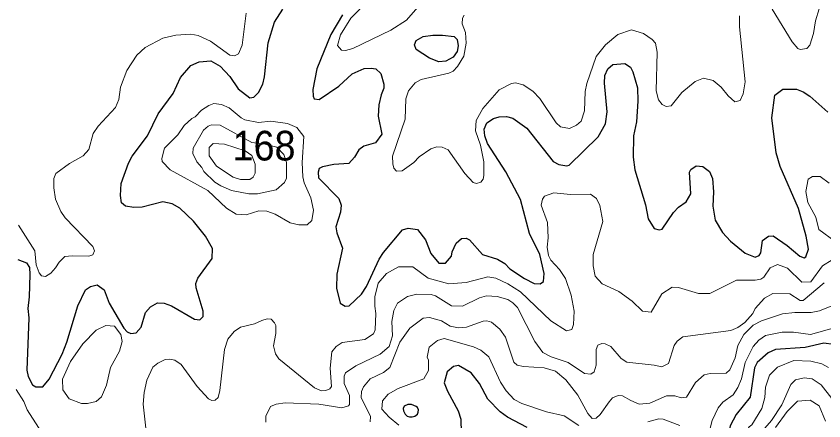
# Model space of a CAD drawing. Extents: x 673.6 to 698.9, y 7012 to 7040.1.
# Drawn here: x 673.738 to 675.914, y 7019.139 to 7020.23 of the extents above; entities that cross this region are included whole.
import ezdxf

# ---------------------------------------------------------------- set-up
doc = ezdxf.new("R2010")
doc.units = 0
doc.header["$LTSCALE"] = 0.032
doc.layers.add('1', color=7, linetype='Continuous', lineweight=25)
doc.layers.add('2', color=7, linetype='Continuous', lineweight=13)
doc.layers.add('21', color=7, linetype='Continuous')

msp = doc.modelspace()

# ---------------------------------------------------------------- linework, layer by layer
at = {"layer": '1'}
for points in [[(673.7433, 7019.5738), (673.7662, 7019.5649), (673.7745, 7019.5519), (673.7754, 7019.5338), (673.7737, 7019.473), (673.7697, 7019.4419), (673.7722, 7019.417), (673.7673, 7019.2755), (673.7709, 7019.2586), (673.7827, 7019.2356), (673.7915, 7019.2307), (673.8099, 7019.2308), (673.827, 7019.2516), (673.8619, 7019.3187), (673.8745, 7019.3507), (673.9043, 7019.4486), (673.9254, 7019.4924), (673.9389, 7019.5012), (673.9568, 7019.5058), (673.975, 7019.4919), (673.9892, 7019.4563), (674.0281, 7019.3886), (674.0377, 7019.3786), (674.0476, 7019.3742), (674.0617, 7019.3763), (674.0747, 7019.391), (674.0871, 7019.4306), (674.0998, 7019.4463), (674.119, 7019.4572), (674.1367, 7019.4565), (674.1567, 7019.4491), (674.2189, 7019.4126), (674.2328, 7019.4113), (674.242, 7019.4201), (674.2421, 7019.4343), (674.2228, 7019.4978), (674.2225, 7019.5095), (674.2279, 7019.5238), (674.2661, 7019.5766), (674.2668, 7019.6033), (674.2484, 7019.6365), (674.2162, 7019.6773), (674.1792, 7019.7119), (674.1583, 7019.7236), (674.1337, 7019.7292), (674.0778, 7019.7147), (674.0552, 7019.7138), (674.0329, 7019.7172), (674.0225, 7019.7267), (674.0194, 7019.7465), (674.0213, 7019.7791), (674.0413, 7019.8338), (674.0511, 7019.8519), (674.0924, 7019.9074), (674.1207, 7019.9663), (674.1616, 7020.0211), (674.1812, 7020.0644), (674.2085, 7020.0967), (674.2311, 7020.1066), (674.2631, 7020.1093), (674.2882, 7020.0949), (674.3142, 7020.0674), (674.3366, 7020.0334), (674.368, 7020.0098), (674.3786, 7020.0114), (674.3911, 7020.0238), (674.4024, 7020.0466), (674.4073, 7020.0663), (674.4172, 7020.158), (674.4341, 7020.2134), (674.4565, 7020.2484)], [(674.617, 7020.2335), (674.5862, 7020.1805), (674.548, 7020.0881), (674.5372, 7020.0318), (674.5381, 7020.0138), (674.5413, 7020.0067), (674.5548, 7020.0055), (674.6075, 7020.0406), (674.6433, 7020.0745), (674.6761, 7020.0884), (674.6941, 7020.09), (674.7075, 7020.088), (674.7209, 7020.0754), (674.7286, 7020.0463), (674.7286, 7020.0356), (674.7217, 7020.018)], [(674.6745, 7019.8789), (674.6609, 7019.869), (674.65, 7019.8497), (674.6348, 7019.8322), (674.5936, 7019.8296), (674.5631, 7019.824), (674.5541, 7019.8192), (674.5519, 7019.8095), (674.5531, 7019.7941), (674.6073, 7019.7381), (674.6135, 7019.7199), (674.6119, 7019.7014), (674.5996, 7019.6619), (674.6022, 7019.6456), (674.617, 7019.6042), (674.6022, 7019.5342), (674.6013, 7019.4964), (674.6112, 7019.4557), (674.6247, 7019.4484), (674.6355, 7019.4493), (674.6689, 7019.4806), (674.6818, 7019.5008), (674.7162, 7019.5746), (674.7276, 7019.5927), (674.7787, 7019.6535), (674.7944, 7019.6586), (674.819, 7019.6545), (674.8406, 7019.6272), (674.8551, 7019.5901), (674.8767, 7019.5643), (674.8949, 7019.5638), (674.911, 7019.5825), (674.9128, 7019.5946), (674.9237, 7019.6178), (674.9374, 7019.6306), (674.9505, 7019.6314), (674.959, 7019.6271), (674.9944, 7019.5873), (675.0343, 7019.5749), (675.0541, 7019.5634), (675.0684, 7019.5484), (675.1074, 7019.5223), (675.1333, 7019.5092), (675.1499, 7019.5085), (675.1582, 7019.5149), (675.1606, 7019.5363), (675.1487, 7019.5877), (675.1205, 7019.6443), (675.0968, 7019.7359), (675.0571, 7019.8103), (675.0082, 7019.8869), (675.0007, 7019.9069), (674.9984, 7019.9253), (675.0062, 7019.9418), (675.0244, 7019.954), (675.0393, 7019.9586), (675.059, 7019.9595), (675.0764, 7019.9548), (675.1137, 7019.9277), (675.1851, 7019.8377), (675.1999, 7019.8296), (675.2213, 7019.8264), (675.2277, 7019.8283), (675.3061, 7019.9041), (675.3253, 7019.9398), (675.3302, 7019.9718), (675.3229, 7020.049), (675.3237, 7020.0696), (675.3317, 7020.0875), (675.3458, 7020.0998), (675.3774, 7020.1024), (675.3931, 7020.092), (675.3995, 7020.0793), (675.4115, 7020.0367), (675.4131, 7020.0006), (675.409, 7019.9447), (675.4009, 7019.9073), (675.4002, 7019.8495), (675.4049, 7019.8152), (675.4336, 7019.7216), (675.4403, 7019.6838), (675.4563, 7019.6576), (675.4701, 7019.6542), (675.4785, 7019.6559), (675.5086, 7019.7006), (675.5224, 7019.7152), (675.5432, 7019.7289), (675.5552, 7019.7512), (675.5521, 7019.8095), (675.5557, 7019.816), (675.5699, 7019.826), (675.5874, 7019.8248), (675.6053, 7019.8109), (675.6136, 7019.7918), (675.6161, 7019.7561)], [(675.7021, 7019.5908), (675.7291, 7019.5799), (675.7391, 7019.5847), (675.7441, 7019.5919), (675.7488, 7019.6254), (675.7642, 7019.6371), (675.7776, 7019.6373), (675.8153, 7019.6112), (675.8492, 7019.5826), (675.8608, 7019.5785), (675.8653, 7019.5812), (675.8725, 7019.6015), (675.866, 7019.637), (675.8456, 7019.711), (675.7956, 7019.8247), (675.7854, 7019.8613), (675.774, 7019.9556), (675.7816, 7020.0171), (675.8033, 7020.0332), (675.8397, 7020.0326), (675.8577, 7020.026), (675.8758, 7020.0145), (675.9248, 7019.9712)], [(674.7217, 7020.018), (674.7155, 7019.9904), (674.7132, 7019.9603), (674.7235, 7019.9119), (674.7058, 7019.8886), (674.6745, 7019.8789)], [(675.6161, 7019.7561), (675.6146, 7019.7176), (675.6211, 7019.6802), (675.6411, 7019.6462), (675.6626, 7019.6236), (675.7021, 7019.5908)], [(675.9399, 7019.345), (675.9136, 7019.3481), (675.8631, 7019.3367), (675.7835, 7019.3308), (675.7641, 7019.3226), (675.7339, 7019.2958), (675.7272, 7019.2816), (675.7155, 7019.2027), (675.6772, 7019.1561), (675.6618, 7019.1256), (675.6419, 7019.0413), (675.6265, 7019.0236), (675.6142, 7019.0217), (675.6028, 7019.0241), (675.5668, 7019.0621), (675.5417, 7019.0746), (675.5031, 7019.0785), (675.4452, 7019.0681), (675.4056, 7019.046), (675.3679, 7019.0077)], [(675.1146, 7019.1206), (675.0616, 7019.1487), (675.042, 7019.1629), (675.0089, 7019.1974), (674.9861, 7019.2393), (674.9638, 7019.2682), (674.93, 7019.288), (674.9161, 7019.2855), (674.8994, 7019.2707), (674.8915, 7019.2414), (674.9005, 7019.2187), (674.9291, 7019.1657), (674.9364, 7019.143), (674.9379, 7019.069)]]:
    msp.add_lwpolyline(points, dxfattribs=at)
for points in [[(674.8862, 7020.1781), (674.9178, 7020.1747), (674.9261, 7020.1671), (674.929, 7020.1494), (674.9257, 7020.1349), (674.9156, 7020.1196), (674.8958, 7020.1085), (674.877, 7020.1067), (674.852, 7020.1168), (674.8159, 7020.1403), (674.811, 7020.1525), (674.8156, 7020.1638), (674.8348, 7020.1751), (674.8602, 7020.1789)], [(674.816, 7019.1777), (674.8034, 7019.1827), (674.793, 7019.1825), (674.7834, 7019.1784), (674.7808, 7019.1718), (674.7812, 7019.1657), (674.786, 7019.1573), (674.7915, 7019.1518), (674.7976, 7019.1501), (674.8047, 7019.1499), (674.8119, 7019.1518), (674.8191, 7019.1566), (674.8215, 7019.1625), (674.8217, 7019.1688), (674.8191, 7019.1751)]]:
    msp.add_lwpolyline(points, close=True, dxfattribs=at)
at = {"layer": '2'}
for points in [[(674.8204, 7020.2544), (674.7894, 7020.2191), (674.7478, 7020.1918), (674.6452, 7020.1429), (674.6255, 7020.1371), (674.6145, 7020.1377), (674.604, 7020.1507), (674.612, 7020.1797), (674.6394, 7020.2242), (674.6894, 7020.2754)], [(674.358, 7020.2378), (674.3472, 7020.1515), (674.3371, 7020.1285), (674.3265, 7020.1231), (674.314, 7020.1243), (674.2616, 7020.1626), (674.2282, 7020.1778), (674.2084, 7020.1813), (674.1684, 7020.1788)], [(674.855, 7019.8722), (674.8237, 7019.8507), (674.8097, 7019.835), (674.7777, 7019.8132), (674.7627, 7019.8123), (674.7552, 7019.8199), (674.7531, 7019.832), (674.7516, 7019.8523), (674.7859, 7019.9517), (674.7879, 7020.0071), (674.7952, 7020.0283), (674.813, 7020.0496), (674.8289, 7020.0589), (674.9034, 7020.0757), (674.9155, 7020.0814), (674.9272, 7020.0941), (674.9438, 7020.1219), (674.9506, 7020.1571), (674.9482, 7020.1853), (674.9399, 7020.2088), (674.9407, 7020.2246), (674.9452, 7020.2325)], [(675.6869, 7020.231), (675.6868, 7020.2006), (675.7016, 7020.0524), (675.6964, 7020.0207), (675.6882, 7020.0024), (675.6735, 7019.9991), (675.6557, 7020.0154), (675.6375, 7020.0384), (675.616, 7020.0567), (675.5896, 7020.0623), (675.5673, 7020.0533), (675.5308, 7020.0244), (675.5026, 7019.9883), (675.4891, 7019.9858), (675.4783, 7019.9914), (675.4683, 7020.0042), (675.4617, 7020.0286), (675.465, 7020.1328), (675.4599, 7020.1566), (675.4512, 7020.1672), (675.4279, 7020.183), (675.3957, 7020.1927), (675.3588, 7020.18), (675.3255, 7020.1527), (675.3005, 7020.1209), (675.2751, 7020.0479), (675.2711, 7020.0269), (675.2693, 7019.9743), (675.2602, 7019.9468), (675.2473, 7019.9361), (675.2288, 7019.9267), (675.2045, 7019.9317), (675.193, 7019.9422), (675.1492, 7020.0074), (675.1299, 7020.0274), (675.1043, 7020.0444), (675.0828, 7020.0497), (675.0728, 7020.0481), (675.0396, 7020.0312), (674.9953, 7019.981), (674.9771, 7019.9487), (674.9753, 7019.9204), (674.9888, 7019.8818), (674.9982, 7019.837), (674.9982, 7019.7998), (674.9957, 7019.7902), (674.9897, 7019.7827), (674.9786, 7019.7788), (674.9695, 7019.7818)], [(675.9008, 7020.2494), (675.891, 7020.217), (675.8857, 7020.1831), (675.8762, 7020.1512), (675.8679, 7020.1423), (675.8502, 7020.1396), (675.8433, 7020.1428), (675.8279, 7020.1603), (675.7749, 7020.2484)], [(674.1684, 7020.1788), (674.1333, 7020.1702), (674.0862, 7020.145), (674.063, 7020.1244), (674.0369, 7020.083), (674.019, 7020.0379)], [(674.019, 7020.0379), (674.0153, 7020.0052), (674.0058, 7019.9832), (673.9593, 7019.9336), (673.9456, 7019.9138), (673.9343, 7019.8701), (673.9192, 7019.8528), (673.8822, 7019.8329), (673.8452, 7019.8055), (673.84, 7019.792), (673.8396, 7019.7669), (673.8444, 7019.7363), (673.8584, 7019.7032), (673.8702, 7019.6864), (673.9447, 7019.6086), (673.9494, 7019.5969), (673.945, 7019.5861), (673.9344, 7019.5824), (673.8892, 7019.5839), (673.8698, 7019.5817), (673.8546, 7019.567), (673.8445, 7019.5509), (673.8318, 7019.537), (673.8177, 7019.528), (673.807, 7019.5296), (673.8004, 7019.5381), (673.7923, 7019.5598), (673.7883, 7019.597), (673.7446, 7019.6664)], [(674.9695, 7019.7818), (674.947, 7019.8052), (674.9023, 7019.8696), (674.8861, 7019.8765), (674.8716, 7019.8773), (674.855, 7019.8722)], [(675.9279, 7019.78), (675.9041, 7019.7973), (675.8832, 7019.7976), (675.8713, 7019.7905), (675.8652, 7019.757), (675.8701, 7019.7273), (675.8921, 7019.6882), (675.8998, 7019.6546), (675.9439, 7019.6225)], [(675.9364, 7019.573), (675.9098, 7019.5571), (675.8784, 7019.5135), (675.854, 7019.5125), (675.8161, 7019.5505), (675.7889, 7019.5599), (675.7689, 7019.551), (675.752, 7019.5263), (675.7435, 7019.5211), (675.7287, 7019.5182), (675.6786, 7019.5181), (675.6068, 7019.4818), (675.5764, 7019.4821), (675.5225, 7019.4984), (675.5052, 7019.4992), (675.4772, 7019.4816), (675.4487, 7019.4315), (675.425, 7019.4348), (675.3975, 7019.4614), (675.3611, 7019.4871), (675.3169, 7019.508), (675.2981, 7019.5293), (675.2923, 7019.5564), (675.2924, 7019.5877), (675.3186, 7019.6765), (675.3104, 7019.7195), (675.3014, 7019.7383), (675.285, 7019.75), (675.2309, 7019.7492), (675.1863, 7019.7533), (675.1611, 7019.7443), (675.1555, 7019.7364), (675.1519, 7019.7206), (675.1691, 7019.6736), (675.1708, 7019.6325), (675.1684, 7019.6067), (675.1725, 7019.5842), (675.1784, 7019.5716), (675.2017, 7019.5464), (675.218, 7019.523), (675.2332, 7019.478), (675.2414, 7019.4349), (675.2398, 7019.3986), (675.235, 7019.385), (675.2203, 7019.3811), (675.1787, 7019.4083), (675.0971, 7019.4867), (675.0627, 7019.508), (675.0302, 7019.5231), (675.0089, 7019.5272), (674.9502, 7019.5116), (674.904, 7019.508), (674.8476, 7019.5231), (674.807, 7019.5541), (674.7682, 7019.5543), (674.7355, 7019.5362), (674.7137, 7019.5097), (674.7047, 7019.4733), (674.704, 7019.4482), (674.7073, 7019.4284), (674.7056, 7019.3843), (674.7011, 7019.3731), (674.6774, 7019.3579), (674.6164, 7019.3498), (674.6, 7019.3394), (674.5883, 7019.325), (674.584, 7019.2812), (674.5873, 7019.2312), (674.583, 7019.2249), (674.5727, 7019.2205), (674.561, 7019.22), (674.5419, 7019.2276), (674.4457, 7019.3064), (674.4367, 7019.3191), (674.4313, 7019.3412), (674.4377, 7019.3745)], [(675.8224, 7019.4811), (675.8497, 7019.4635), (675.8584, 7019.4632), (675.9146, 7019.5107)], [(674.4112, 7019.1356), (674.4105, 7019.1514), (674.4237, 7019.1777), (674.4384, 7019.1839), (674.4633, 7019.1878), (674.5532, 7019.1837), (674.6157, 7019.174), (674.6333, 7019.1791), (674.636, 7019.1829), (674.6366, 7019.2071), (674.6219, 7019.2397), (674.6219, 7019.259), (674.6253, 7019.2683), (674.6531, 7019.2873), (674.7184, 7019.3187), (674.7426, 7019.339), (674.7516, 7019.3682), (674.7501, 7019.4068), (674.7552, 7019.4359), (674.7651, 7019.4558), (674.7924, 7019.4745), (674.8175, 7019.4803), (674.8565, 7019.4796), (674.8678, 7019.4757), (674.9105, 7019.4487), (674.9407, 7019.4476), (674.9864, 7019.4704), (675.0052, 7019.4763), (675.034, 7019.4739), (675.0623, 7019.4656), (675.0761, 7019.4573), (675.0886, 7019.4448), (675.1356, 7019.3527), (675.1567, 7019.3235), (675.1789, 7019.3118), (675.2247, 7019.2965), (675.2691, 7019.2662), (675.2858, 7019.2643), (675.2948, 7019.2709), (675.3006, 7019.289), (675.3007, 7019.3313), (675.305, 7019.3431), (675.3155, 7019.3472), (675.3248, 7019.3464), (675.3404, 7019.3397), (675.3674, 7019.3068), (675.3835, 7019.2969), (675.4564, 7019.289), (675.477, 7019.2841), (675.4953, 7019.2935), (675.5103, 7019.3418), (675.5187, 7019.3541), (675.5341, 7019.3649), (675.6632, 7019.3824), (675.6824, 7019.3907), (675.7005, 7019.4036)], [(675.7005, 7019.4036), (675.7222, 7019.4282), (675.7289, 7019.4418), (675.7537, 7019.4692), (675.7763, 7019.4824), (675.8224, 7019.4811)], [(675.935, 7019.4491), (675.9018, 7019.4352), (675.8795, 7019.4311), (675.8357, 7019.431), (675.8019, 7019.427), (675.746, 7019.4089), (675.7236, 7019.3966), (675.6981, 7019.372), (675.6821, 7019.3418), (675.6752, 7019.3083)], [(674.4, 7019.4096), (674.3799, 7019.4007), (674.3425, 7019.3916), (674.3255, 7019.3799), (674.3087, 7019.3593), (674.2999, 7019.3308), (674.2866, 7019.2203), (674.2823, 7019.2019), (674.2746, 7019.1945), (674.2656, 7019.1937), (674.2561, 7019.198), (674.2257, 7019.2314), (674.1831, 7019.2912), (674.1661, 7019.3021), (674.1525, 7019.3053), (674.14, 7019.3039), (674.1196, 7019.2942), (674.1062, 7019.2835), (674.0906, 7019.2484), (674.0833, 7019.2154), (674.0803, 7019.1837), (674.0893, 7019.1032)], [(674.4377, 7019.3745), (674.4377, 7019.3957), (674.4341, 7019.4035), (674.4253, 7019.4126), (674.4141, 7019.4141), (674.4, 7019.4096)], [(675.568, 7019.2423), (675.5442, 7019.2026), (675.5298, 7019.2011), (675.5126, 7019.2067), (675.4897, 7019.2059), (675.4449, 7019.1862), (675.416, 7019.1838), (675.3941, 7019.1937), (675.371, 7019.2064), (675.3598, 7019.2071), (675.3449, 7019.2011), (675.3354, 7019.1897), (675.3111, 7019.1556), (675.3002, 7019.146), (675.2898, 7019.1453), (675.2779, 7019.1583), (675.2507, 7019.2081), (675.2189, 7019.2497), (675.1908, 7019.2731), (675.16, 7019.2822), (675.1046, 7019.2854), (675.0873, 7019.289), (675.0786, 7019.2973), (675.0559, 7019.3641), (675.0407, 7019.3862), (675.0182, 7019.4045), (675.0062, 7019.4088), (674.9958, 7019.4079), (674.9517, 7019.3912), (674.9301, 7019.3893), (674.9075, 7019.3943), (674.8837, 7019.4086), (674.8519, 7019.4179), (674.8342, 7019.416), (674.7988, 7019.3886), (674.7715, 7019.3514), (674.745, 7019.2831), (674.7277, 7019.2696), (674.6916, 7019.2525), (674.6741, 7019.2308), (674.6686, 7019.2183), (674.6679, 7019.2014), (674.6924, 7019.1509), (674.6916, 7019.1364)], [(675.8318, 7019.3777), (675.8779, 7019.372), (675.9446, 7019.3909)], [(674.7692, 7019.1274), (674.7426, 7019.1484), (674.7232, 7019.1707), (674.7251, 7019.1929), (674.7402, 7019.2104), (674.7675, 7019.2261), (674.8367, 7019.2524), (674.8487, 7019.2749), (674.8486, 7019.3026), (674.8453, 7019.3107), (674.8503, 7019.3371), (674.8728, 7019.3556), (674.8911, 7019.3611), (674.9705, 7019.3381), (674.9897, 7019.3293), (675.0113, 7019.3111), (675.0426, 7019.2429), (675.0578, 7019.2194), (675.0798, 7019.1968), (675.1004, 7019.1853), (675.1666, 7019.163), (675.2144, 7019.1524), (675.254, 7019.1259)], [(675.7018, 7019.2958), (675.7237, 7019.3396), (675.7384, 7019.356), (675.7568, 7019.369), (675.8014, 7019.3778), (675.8318, 7019.3777)], [(675.6752, 7019.3083), (675.6607, 7019.2762), (675.6502, 7019.2675), (675.6079, 7019.2667), (675.5916, 7019.2633), (675.568, 7019.2423)], [(675.602, 7019.0977), (675.6125, 7019.1402), (675.6292, 7019.1736), (675.6418, 7019.1888), (675.6692, 7019.209), (675.6821, 7019.2285), (675.6916, 7019.2525), (675.7018, 7019.2958)], [(675.6024, 7019.0059), (675.6189, 7019.0023), (675.6331, 7019.0061), (675.6405, 7019.0138), (675.6463, 7019.0263), (675.68, 7019.0685), (675.7127, 7019.1229), (675.7198, 7019.1282), (675.7468, 7019.1722), (675.755, 7019.2019), (675.7567, 7019.23), (675.7674, 7019.2618), (675.7887, 7019.2833), (675.833, 7019.3012), (675.8788, 7019.2997), (675.9084, 7019.2923), (675.9261, 7019.2825)], [(675.9348, 7019.199), (675.9065, 7019.236), (675.8825, 7019.2518), (675.861, 7019.2544), (675.8373, 7019.2497), (675.8248, 7019.2368), (675.8009, 7019.1821), (675.7725, 7019.1397)], [(673.8145, 7019.096), (673.7683, 7019.1686), (673.7594, 7019.191), (673.7384, 7019.2233)], [(675.7837, 7019.1205), (675.8153, 7019.1643), (675.8423, 7019.1918), (675.8771, 7019.1944), (675.9006, 7019.1793), (675.9185, 7019.1382)], [(675.4393, 7019.1364), (675.4696, 7019.1442), (675.4813, 7019.1434), (675.5254, 7019.1264)], [(675.7725, 7019.1397), (675.7545, 7019.1191), (675.7236, 7019.0948), (675.7012, 7019.0717), (675.6473, 7018.9974), (675.6316, 7018.9874)]]:
    msp.add_lwpolyline(points, dxfattribs=at)
for points in [[(674.5089, 7019.8351), (674.5102, 7019.7969), (674.514, 7019.7801), (674.5318, 7019.7397), (674.5396, 7019.7072), (674.5349, 7019.6789), (674.5219, 7019.6676), (674.4999, 7019.667), (674.476, 7019.673), (674.4362, 7019.696), (674.4139, 7019.7038), (674.3917, 7019.7047), (674.3576, 7019.6939), (674.331, 7019.6963), (674.3053, 7019.7124), (674.2543, 7019.7596), (674.1529, 7019.8153), (674.132, 7019.8382), (674.1305, 7019.8458), (674.138, 7019.874), (674.1738, 7019.9099), (674.1907, 7019.9351), (674.2111, 7019.954), (674.2208, 7019.9588), (674.2375, 7019.9761), (674.2571, 7019.989), (674.2711, 7019.9942), (674.2916, 7019.9915), (674.3125, 7019.9827), (674.3442, 7019.9554), (674.3546, 7019.9503), (674.3914, 7019.9431), (674.4246, 7019.9463), (674.469, 7019.9405), (674.4942, 7019.93), (674.5133, 7019.9056)], [(674.4389, 7019.7617), (674.4614, 7019.7815), (674.4669, 7019.7928), (674.4669, 7019.8353), (674.4594, 7019.8566), (674.4401, 7019.8764), (674.409, 7019.8846), (674.3729, 7019.8891), (674.2875, 7019.9358), (674.2646, 7019.937), (674.2552, 7019.9334), (674.2433, 7019.922), (674.2148, 7019.8736), (674.2145, 7019.8596), (674.2247, 7019.8367), (674.2388, 7019.8222), (674.2436, 7019.811), (674.2736, 7019.7826), (674.29, 7019.772), (674.3182, 7019.7601), (674.3647, 7019.7508), (674.3888, 7019.7508)], [(674.355, 7019.8668), (674.3731, 7019.8543), (674.3825, 7019.8306), (674.3821, 7019.8065), (674.3764, 7019.796), (674.3673, 7019.7893), (674.3423, 7019.7895), (674.323, 7019.7958), (674.2781, 7019.8258), (674.2578, 7019.8531), (674.2586, 7019.8753), (674.2689, 7019.8863), (674.2994, 7019.8848)], [(674.0029, 7019.394), (674.0201, 7019.3713), (674.0235, 7019.3528), (674.0169, 7019.3264), (673.9928, 7019.2829), (673.9821, 7019.2353), (673.9679, 7019.2034), (673.954, 7019.1914), (673.9306, 7019.1855), (673.9142, 7019.1856), (673.8808, 7019.198), (673.8639, 7019.2229), (673.8633, 7019.2508), (673.8849, 7019.2991), (673.9178, 7019.3467), (673.954, 7019.3836), (673.9799, 7019.3956)]]:
    msp.add_lwpolyline(points, close=True, dxfattribs=at)

# ---------------------------------------------------------------- texts
at = {"layer": '21', "width": 0.95}
msp.add_text('168', height=0.08, dxfattribs=at).set_placement((674.3212, 7019.8407))

doc.saveas('drawing.dxf')
